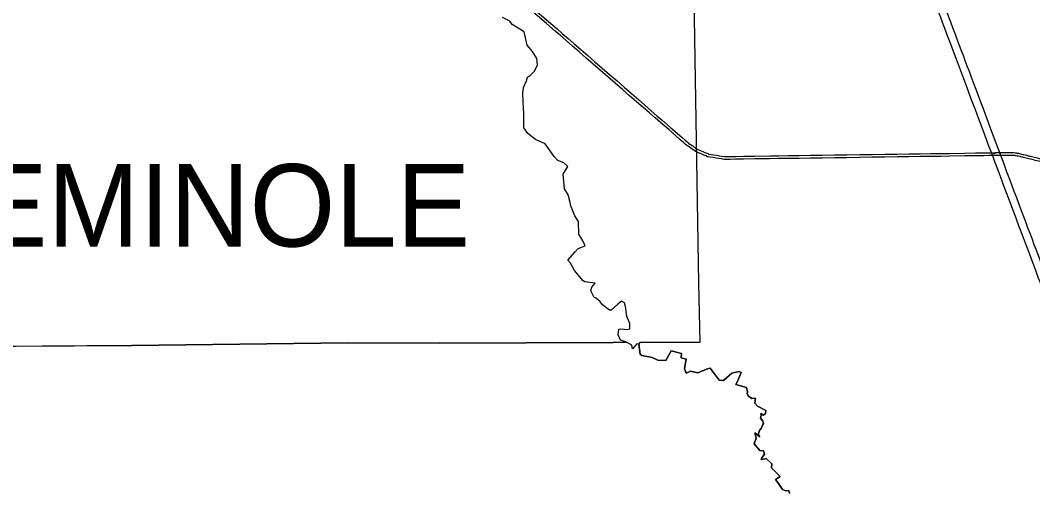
# Model space of a CAD drawing. Extents: x -830013.9 to -829988.1, y 1290300 to 1290310.6.
# Drawn here: x -829994.56 to -829993.884, y 1290308.217 to 1290308.531 of the extents above; entities that cross this region are included whole.
import ezdxf

# ---------------------------------------------------------------- set-up
doc = ezdxf.new("R2010")
doc.units = 0
for name, color, linetype in [('FLMap5', 7, 'Continuous'), ('Miscellaneous6', 7, 'Continuous'), ('TextPtLabel', 7, 'Continuous')]:
    doc.layers.add(name, color=color, linetype=linetype)

msp = doc.modelspace()

# ---------------------------------------------------------------- linework, layer by layer
at = {"layer": 'FLMap5'}
for p, q in [((-829994.11353, 1290308.73255), (-829994.10743, 1290308.35594)), ((-829994.10743, 1290308.35594), (-829994.10656, 1290308.31622)), ((-829994.1467, 1290308.31633), (-829994.14733, 1290308.31525)), ((-829994.10656, 1290308.31622), (-829994.1467, 1290308.31633)), ((-829994.48571, 1290308.31433), (-829994.60155, 1290308.31352)), ((-829994.14733, 1290308.31525), (-829994.14651, 1290308.30843)), ((-829994.12567, 1290308.31081), (-829994.12938, 1290308.3042)), ((-829994.12938, 1290308.3042), (-829994.12567, 1290308.31081)), ((-829994.11886, 1290308.30895), (-829994.12567, 1290308.31081)), ((-829994.12567, 1290308.31081), (-829994.11886, 1290308.30895)), ((-829994.14651, 1290308.30843), (-829994.14527, 1290308.3075)), ((-829994.13846, 1290308.30627), (-829994.14527, 1290308.3075)), ((-829994.14527, 1290308.3075), (-829994.13846, 1290308.30627)), ((-829994.13464, 1290308.30441), (-829994.13846, 1290308.30627)), ((-829994.13846, 1290308.30627), (-829994.13464, 1290308.30441)), ((-829994.12938, 1290308.3042), (-829994.13464, 1290308.30441)), ((-829994.13464, 1290308.30441), (-829994.12938, 1290308.3042)), ((-829994.11903, 1290308.30614), (-829994.11886, 1290308.30895)), ((-829994.11886, 1290308.30895), (-829994.11903, 1290308.30614)), ((-829994.11573, 1290308.30526), (-829994.11903, 1290308.30614)), ((-829994.11903, 1290308.30614), (-829994.11573, 1290308.30526)), ((-829994.11679, 1290308.299), (-829994.11573, 1290308.30526)), ((-829994.11573, 1290308.30526), (-829994.11679, 1290308.299)), ((-829994.11573, 1290308.29588), (-829994.11679, 1290308.299)), ((-829994.11679, 1290308.299), (-829994.11573, 1290308.29588)), ((-829994.11284, 1290308.29712), (-829994.11573, 1290308.29588)), ((-829994.11573, 1290308.29588), (-829994.11284, 1290308.29712)), ((-829994.10789, 1290308.29605), (-829994.11284, 1290308.29712)), ((-829994.11284, 1290308.29712), (-829994.10789, 1290308.29605)), ((-829994.10205, 1290308.29859), (-829994.10789, 1290308.29605)), ((-829994.10789, 1290308.29605), (-829994.10205, 1290308.29859)), ((-829994.10205, 1290308.29859), (-829994.09964, 1290308.29918)), ((-829994.09964, 1290308.29918), (-829994.09368, 1290308.2911)), ((-829994.08525, 1290308.29576), (-829994.09079, 1290308.29092)), ((-829994.09079, 1290308.29092), (-829994.08525, 1290308.29576)), ((-829994.08525, 1290308.29576), (-829994.08054, 1290308.29688)), ((-829994.08066, 1290308.2924), (-829994.07895, 1290308.29635)), ((-829994.07895, 1290308.29635), (-829994.08066, 1290308.2924)), ((-829994.08054, 1290308.29688), (-829994.07895, 1290308.29635)), ((-829994.09079, 1290308.29092), (-829994.09368, 1290308.2911)), ((-829994.09368, 1290308.2911), (-829994.09079, 1290308.29092)), ((-829994.08254, 1290308.28821), (-829994.08166, 1290308.28974)), ((-829994.08166, 1290308.28974), (-829994.08254, 1290308.28821)), ((-829994.08166, 1290308.28974), (-829994.08066, 1290308.2924)), ((-829994.08066, 1290308.2924), (-829994.08166, 1290308.28974)), ((-829994.0755, 1290308.2863), (-829994.08254, 1290308.28821)), ((-829994.08254, 1290308.28821), (-829994.0755, 1290308.2863)), ((-829994.0748, 1290308.28347), (-829994.0755, 1290308.2863)), ((-829994.0755, 1290308.2863), (-829994.0748, 1290308.28347)), ((-829994.07491, 1290308.28217), (-829994.0748, 1290308.28347)), ((-829994.0748, 1290308.28347), (-829994.07491, 1290308.28217)), ((-829994.07427, 1290308.2807), (-829994.07491, 1290308.28217)), ((-829994.07491, 1290308.28217), (-829994.07427, 1290308.2807)), ((-829994.07197, 1290308.27893), (-829994.07427, 1290308.2807)), ((-829994.07427, 1290308.2807), (-829994.07197, 1290308.27893)), ((-829994.06955, 1290308.27923), (-829994.07197, 1290308.27893)), ((-829994.07197, 1290308.27893), (-829994.06955, 1290308.27923)), ((-829994.06996, 1290308.2758), (-829994.06955, 1290308.27923)), ((-829994.06955, 1290308.27923), (-829994.06996, 1290308.2758)), ((-829994.06808, 1290308.27374), (-829994.06996, 1290308.2758)), ((-829994.06996, 1290308.2758), (-829994.06808, 1290308.27374)), ((-829994.06248, 1290308.27085), (-829994.06808, 1290308.27374)), ((-829994.06808, 1290308.27374), (-829994.06248, 1290308.27085)), ((-829994.06572, 1290308.26784), (-829994.06589, 1290308.2689)), ((-829994.06589, 1290308.2689), (-829994.06419, 1290308.26784)), ((-829994.06419, 1290308.26784), (-829994.06589, 1290308.2689)), ((-829994.06589, 1290308.2689), (-829994.06572, 1290308.26784)), ((-829994.06419, 1290308.26784), (-829994.06289, 1290308.2689)), ((-829994.06289, 1290308.2689), (-829994.06419, 1290308.26784)), ((-829994.06289, 1290308.2689), (-829994.06248, 1290308.27085)), ((-829994.06248, 1290308.27085), (-829994.06289, 1290308.2689)), ((-829994.06613, 1290308.26584), (-829994.06572, 1290308.26784)), ((-829994.06572, 1290308.26784), (-829994.06613, 1290308.26584)), ((-829994.06466, 1290308.26371), (-829994.06613, 1290308.26584)), ((-829994.06613, 1290308.26584), (-829994.06466, 1290308.26371)), ((-829994.06466, 1290308.26371), (-829994.06419, 1290308.2623)), ((-829994.06419, 1290308.2623), (-829994.0646, 1290308.26153)), ((-829994.06666, 1290308.25327), (-829994.0699, 1290308.25611)), ((-829994.0699, 1290308.25611), (-829994.06896, 1290308.25251)), ((-829994.06743, 1290308.25546), (-829994.06684, 1290308.25764)), ((-829994.06684, 1290308.25764), (-829994.06743, 1290308.25546)), ((-829994.06737, 1290308.25451), (-829994.06743, 1290308.25546)), ((-829994.06743, 1290308.25546), (-829994.06737, 1290308.25451)), ((-829994.06684, 1290308.25764), (-829994.06536, 1290308.25935)), ((-829994.06536, 1290308.25935), (-829994.06684, 1290308.25764)), ((-829994.06536, 1290308.25935), (-829994.0646, 1290308.26153)), ((-829994.0646, 1290308.26153), (-829994.06536, 1290308.25935)), ((-829994.07037, 1290308.24867), (-829994.06896, 1290308.25251)), ((-829994.06896, 1290308.25251), (-829994.07037, 1290308.24867)), ((-829994.06662, 1290308.24418), (-829994.07037, 1290308.24867)), ((-829994.07037, 1290308.24867), (-829994.06662, 1290308.24418)), ((-829994.06666, 1290308.25327), (-829994.06737, 1290308.25451)), ((-829994.06737, 1290308.25451), (-829994.06666, 1290308.25327)), ((-829994.06662, 1290308.24418), (-829994.0642, 1290308.24401)), ((-829994.06349, 1290308.24188), (-829994.06532, 1290308.23929)), ((-829994.0642, 1290308.24401), (-829994.06349, 1290308.24188)), ((-829994.06532, 1290308.23929), (-829994.06567, 1290308.23811)), ((-829994.06314, 1290308.23864), (-829994.06567, 1290308.23811)), ((-829994.06567, 1290308.23811), (-829994.06314, 1290308.23864)), ((-829994.06237, 1290308.23882), (-829994.06314, 1290308.23864)), ((-829994.06314, 1290308.23864), (-829994.06237, 1290308.23882)), ((-829994.05866, 1290308.23539), (-829994.06237, 1290308.23882)), ((-829994.06237, 1290308.23882), (-829994.05866, 1290308.23539)), ((-829994.05872, 1290308.23274), (-829994.05866, 1290308.23539)), ((-829994.05866, 1290308.23539), (-829994.05872, 1290308.23274)), ((-829994.05294, 1290308.22678), (-829994.05872, 1290308.23274)), ((-829994.05872, 1290308.23274), (-829994.05294, 1290308.22678)), ((-829994.05294, 1290308.22678), (-829994.05612, 1290308.2249)), ((-829994.05612, 1290308.2249), (-829994.05465, 1290308.22283)), ((-829994.05153, 1290308.21811), (-829994.05465, 1290308.22283)), ((-829994.05465, 1290308.22283), (-829994.05153, 1290308.21811)), ((-829994.04911, 1290308.21735), (-829994.05153, 1290308.21811)), ((-829994.05153, 1290308.21811), (-829994.04911, 1290308.21735)), ((-829994.04728, 1290308.21758), (-829994.04911, 1290308.21735)), ((-829994.04911, 1290308.21735), (-829994.04728, 1290308.21758)), ((-829994.04687, 1290308.21558), (-829994.04728, 1290308.21758)), ((-829994.04728, 1290308.21758), (-829994.04687, 1290308.21558))]:
    msp.add_line(p, q, dxfattribs=at)
for points in [[(-829994.15548, 1290308.31659), (-829994.15948, 1290308.31778), (-829994.16116, 1290308.32135), (-829994.16072, 1290308.32519), (-829994.15931, 1290308.3254), (-829994.1548, 1290308.32492), (-829994.15335, 1290308.32536), (-829994.15328, 1290308.32887), (-829994.1554, 1290308.33365), (-829994.15629, 1290308.34035), (-829994.15688, 1290308.34277), (-829994.15889, 1290308.34378), (-829994.16142, 1290308.34189), (-829994.16578, 1290308.33788), (-829994.1669, 1290308.33782), (-829994.17144, 1290308.34147), (-829994.17333, 1290308.34383), (-829994.17633, 1290308.34602), (-829994.17716, 1290308.34631), (-829994.17934, 1290308.35085), (-829994.17857, 1290308.35315), (-829994.17639, 1290308.35581), (-829994.18323, 1290308.35669), (-829994.18435, 1290308.3574), (-829994.1903, 1290308.36436), (-829994.19297, 1290308.36914), (-829994.19462, 1290308.37121), (-829994.18977, 1290308.37668), (-829994.18771, 1290308.37895), (-829994.18317, 1290308.38081), (-829994.18472, 1290308.38411), (-829994.1873, 1290308.38855), (-829994.18751, 1290308.39701), (-829994.18998, 1290308.40073), (-829994.19266, 1290308.40744), (-829994.19308, 1290308.4096), (-829994.19452, 1290308.41487), (-829994.19689, 1290308.41879), (-829994.1979, 1290308.42862), (-829994.1947, 1290308.43368), (-829994.19739, 1290308.43616), (-829994.20141, 1290308.43781), (-829994.20378, 1290308.44039), (-829994.20987, 1290308.44885), (-829994.21616, 1290308.45174), (-829994.22132, 1290308.45566), (-829994.2241, 1290308.45959), (-829994.22405, 1290308.46954), (-829994.22435, 1290308.4719), (-829994.22476, 1290308.48275), (-829994.22429, 1290308.48652), (-829994.22228, 1290308.49083), (-829994.22169, 1290308.49337), (-829994.22004, 1290308.49431), (-829994.21693, 1290308.49728), (-829994.21484, 1290308.50145), (-829994.21545, 1290308.50587), (-829994.21824, 1290308.51045), (-829994.22191, 1290308.51477), (-829994.22375, 1290308.52352), (-829994.23183, 1290308.52842), (-829994.23342, 1290308.53072), (-829994.23837, 1290308.53308)], [(-829994.60155, 1290308.31352), (-829994.48571, 1290308.31433), (-829994.34157, 1290308.3161), (-829994.28059, 1290308.31588), (-829994.16446, 1290308.31623), (-829994.15548, 1290308.31659)], [(-829994.28059, 1290308.31588), (-829994.34157, 1290308.3161), (-829994.48571, 1290308.31433)], [(-829994.15548, 1290308.31659), (-829994.16446, 1290308.31623), (-829994.28059, 1290308.31588)], [(-829994.14527, 1290308.3075), (-829994.14651, 1290308.30843), (-829994.14733, 1290308.31525), (-829994.14867, 1290308.31545), (-829994.15156, 1290308.31215), (-829994.15208, 1290308.31442), (-829994.15548, 1290308.31659)], [(-829994.09368, 1290308.2911), (-829994.09964, 1290308.29918), (-829994.10205, 1290308.29859)], [(-829994.07895, 1290308.29635), (-829994.08054, 1290308.29688), (-829994.08525, 1290308.29576)], [(-829994.0646, 1290308.26153), (-829994.06419, 1290308.2623), (-829994.06466, 1290308.26371)], [(-829994.06896, 1290308.25251), (-829994.0699, 1290308.25611), (-829994.06666, 1290308.25327)], [(-829994.06567, 1290308.23811), (-829994.06532, 1290308.23929), (-829994.06349, 1290308.24188), (-829994.0642, 1290308.24401), (-829994.06662, 1290308.24418)], [(-829994.05465, 1290308.22283), (-829994.05612, 1290308.2249), (-829994.05294, 1290308.22678)]]:
    msp.add_lwpolyline(points, dxfattribs=at)
at = {"layer": 'Miscellaneous6'}
for points in [[(-829993.87007, 1290308.10739), (-829993.87007, 1290308.10739), (-829993.86865, 1290308.32911), (-829993.86865, 1290308.32911), (-829993.86865, 1290308.32911), (-829993.86865, 1290308.32921), (-829993.86865, 1290308.32921), (-829993.86865, 1290308.32921), (-829993.86905, 1290308.34164), (-829993.86905, 1290308.34164), (-829993.86906, 1290308.3418), (-829993.86907, 1290308.34194), (-829993.86911, 1290308.34209), (-829993.86911, 1290308.34209), (-829993.86967, 1290308.34482), (-829993.86967, 1290308.34482), (-829993.86971, 1290308.34498), (-829993.86973, 1290308.34507), (-829993.86978, 1290308.34522), (-829993.86978, 1290308.34522), (-829993.94439, 1290308.54402), (-829993.94439, 1290308.54402), (-829993.9469, 1290308.55034), (-829993.9503, 1290308.55766), (-829993.9483, 1290308.56457), (-829993.9483, 1290308.56457), (-829993.93976, 1290308.60123), (-829993.93976, 1290308.60123), (-829993.93973, 1290308.60134), (-829993.93973, 1290308.60135), (-829993.93971, 1290308.60146), (-829993.93971, 1290308.60146), (-829993.93896, 1290308.60683), (-829993.93896, 1290308.60683), (-829993.93896, 1290308.60683), (-829993.93894, 1290308.60699), (-829993.93894, 1290308.60699), (-829993.93894, 1290308.60699), (-829993.93865, 1290308.61066), (-829993.93865, 1290308.61066), (-829993.93864, 1290308.61082), (-829993.93864, 1290308.611), (-829993.93866, 1290308.61116), (-829993.93866, 1290308.61116), (-829993.93895, 1290308.61386), (-829993.93895, 1290308.61386), (-829993.93903, 1290308.61795), (-829993.93983, 1290308.622), (-829993.94075, 1290308.62597), (-829993.94075, 1290308.62597), (-829993.95473, 1290308.6808), (-829993.96915, 1290308.73733)], [(-829993.94397, 1290308.61083), (-829993.94397, 1290308.61083), (-829993.94423, 1290308.60749), (-829993.94423, 1290308.60749), (-829993.94423, 1290308.60749), (-829993.94496, 1290308.60232), (-829993.94496, 1290308.60232), (-829993.94496, 1290308.60232), (-829993.9535, 1290308.5657), (-829993.9535, 1290308.5657), (-829993.9535, 1290308.5657), (-829993.95353, 1290308.56555), (-829993.95353, 1290308.56555), (-829993.95353, 1290308.56555), (-829993.95414, 1290308.56201), (-829993.95414, 1290308.56201), (-829993.95417, 1290308.56185), (-829993.95418, 1290308.56171), (-829993.95418, 1290308.56155), (-829993.95418, 1290308.56155), (-829993.95418, 1290308.55882), (-829993.95418, 1290308.55882), (-829993.95418, 1290308.5587), (-829993.95418, 1290308.5586), (-829993.95416, 1290308.55849), (-829993.95416, 1290308.55849), (-829993.95372, 1290308.55489), (-829993.95372, 1290308.55489), (-829993.9537, 1290308.55473), (-829993.95368, 1290308.55462), (-829993.95363, 1290308.55447), (-829993.95363, 1290308.55447), (-829993.95249, 1290308.55057), (-829993.95249, 1290308.55057), (-829993.95249, 1290308.55057), (-829993.95247, 1290308.55051), (-829993.95247, 1290308.55051), (-829993.95247, 1290308.55051), (-829993.95146, 1290308.54733), (-829993.95146, 1290308.54733), (-829993.95146, 1290308.54733), (-829993.95139, 1290308.54714), (-829993.95139, 1290308.54714), (-829993.95139, 1290308.54714), (-829993.94935, 1290308.54213), (-829993.94935, 1290308.54213), (-829993.94935, 1290308.54213), (-829993.87484, 1290308.34354), (-829993.87484, 1290308.34354)], [(-829994.41868, 1290308.59537), (-829994.41868, 1290308.59537), (-829994.3315, 1290308.56471), (-829994.3315, 1290308.56471), (-829994.3315, 1290308.56471), (-829994.28392, 1290308.5587), (-829994.28392, 1290308.5587), (-829994.28392, 1290308.5587), (-829994.25493, 1290308.55447), (-829994.25493, 1290308.55447), (-829994.25493, 1290308.55447), (-829994.23591, 1290308.55122), (-829994.23591, 1290308.55122), (-829994.23591, 1290308.55122), (-829994.22924, 1290308.54732), (-829994.22924, 1290308.54732), (-829994.22924, 1290308.54732), (-829994.22068, 1290308.53931), (-829994.22068, 1290308.53931), (-829994.22068, 1290308.53931), (-829994.11537, 1290308.44787), (-829994.11537, 1290308.44787), (-829994.11537, 1290308.44787), (-829994.10949, 1290308.44375), (-829994.10949, 1290308.44375), (-829994.10949, 1290308.44375), (-829994.10125, 1290308.4402), (-829994.10125, 1290308.4402), (-829994.10125, 1290308.4402), (-829994.0901, 1290308.43844), (-829994.0901, 1290308.43844), (-829994.0901, 1290308.43844), (-829993.90985, 1290308.44101), (-829993.90985, 1290308.44101), (-829993.90985, 1290308.44101), (-829993.90984, 1290308.44101), (-829993.90984, 1290308.44101), (-829993.90984, 1290308.44101), (-829993.90961, 1290308.44102), (-829993.90922, 1290308.44104), (-829993.90802, 1290308.44108), (-829993.90527, 1290308.44116), (-829993.90244, 1290308.44116), (-829993.89984, 1290308.44117), (-829993.89714, 1290308.44109), (-829993.89563, 1290308.44086), (-829993.89482, 1290308.44074), (-829993.89299, 1290308.44032), (-829993.8907, 1290308.43976), (-829993.88726, 1290308.43892), (-829993.88271, 1290308.43777), (-829993.87847, 1290308.43683), (-829993.87633, 1290308.43636), (-829993.87428, 1290308.43594), (-829993.87248, 1290308.43563), (-829993.87067, 1290308.43533), (-829993.86911, 1290308.43514), (-829993.86792, 1290308.43514), (-829993.86724, 1290308.43515), (-829993.86668, 1290308.43519), (-829993.86613, 1290308.43541), (-829993.86613, 1290308.43541), (-829993.86613, 1290308.43541), (-829993.86613, 1290308.43541), (-829993.86451, 1290308.4361), (-829993.86237, 1290308.43715), (-829993.86062, 1290308.43802), (-829993.85888, 1290308.4389), (-829993.85754, 1290308.43961), (-829993.85754, 1290308.43961), (-829993.85754, 1290308.43961), (-829993.85843, 1290308.4413), (-829993.85843, 1290308.4413), (-829993.85843, 1290308.4413), (-829993.85876, 1290308.44113), (-829993.8593, 1290308.44084), (-829993.86095, 1290308.43999), (-829993.86455, 1290308.43816), (-829993.86688, 1290308.43717), (-829993.86688, 1290308.43717), (-829993.86688, 1290308.43717), (-829993.86688, 1290308.43717), (-829993.86696, 1290308.43713), (-829993.86736, 1290308.43705), (-829993.86792, 1290308.43706), (-829993.86925, 1290308.43705), (-829993.87146, 1290308.43737), (-829993.874, 1290308.43786), (-829993.87783, 1290308.43859), (-829993.88247, 1290308.43971), (-829993.88649, 1290308.44069), (-829993.8885, 1290308.44119), (-829993.89036, 1290308.44165), (-829993.89188, 1290308.44201), (-829993.89341, 1290308.44238), (-829993.8946, 1290308.44264), (-829993.89534, 1290308.44275), (-829993.89708, 1290308.44301), (-829993.89979, 1290308.44308), (-829993.90244, 1290308.44308), (-829993.90626, 1290308.44308), (-829993.90991, 1290308.44293), (-829993.90992, 1290308.44293), (-829993.90992, 1290308.44293), (-829993.90988, 1290308.44197), (-829993.90988, 1290308.44197), (-829993.90988, 1290308.44197), (-829993.90989, 1290308.44293), (-829993.90989, 1290308.44293), (-829993.90989, 1290308.44293), (-829994.08997, 1290308.44035), (-829994.08997, 1290308.44035), (-829994.08997, 1290308.44035), (-829994.10071, 1290308.44205), (-829994.10071, 1290308.44205), (-829994.10071, 1290308.44205), (-829994.10856, 1290308.44543), (-829994.10856, 1290308.44543), (-829994.10856, 1290308.44543), (-829994.11419, 1290308.44938), (-829994.11419, 1290308.44938), (-829994.11419, 1290308.44938), (-829994.2194, 1290308.54073), (-829994.2194, 1290308.54073), (-829994.2194, 1290308.54073), (-829994.22809, 1290308.54886), (-829994.22809, 1290308.54886), (-829994.22809, 1290308.54886), (-829994.23524, 1290308.55305), (-829994.23524, 1290308.55305), (-829994.23524, 1290308.55305), (-829994.25462, 1290308.55636), (-829994.25462, 1290308.55636), (-829994.25462, 1290308.55636), (-829994.28367, 1290308.5606), (-829994.28367, 1290308.5606), (-829994.28367, 1290308.5606), (-829994.33106, 1290308.56658), (-829994.33106, 1290308.56658), (-829994.33106, 1290308.56658), (-829994.41805, 1290308.59717), (-829994.41805, 1290308.59717), (-829994.41805, 1290308.59717), (-829994.41868, 1290308.59536), (-829994.41868, 1290308.59536)]]:
    msp.add_open_spline(points, degree=3, dxfattribs=at)

# ---------------------------------------------------------------- texts
at = {"layer": 'TextPtLabel'}
msp.add_text('SEMINOLE', height=0.055, rotation=360, dxfattribs=at).set_placement((-829994.63998, 1290308.38031))

doc.saveas('drawing.dxf')
